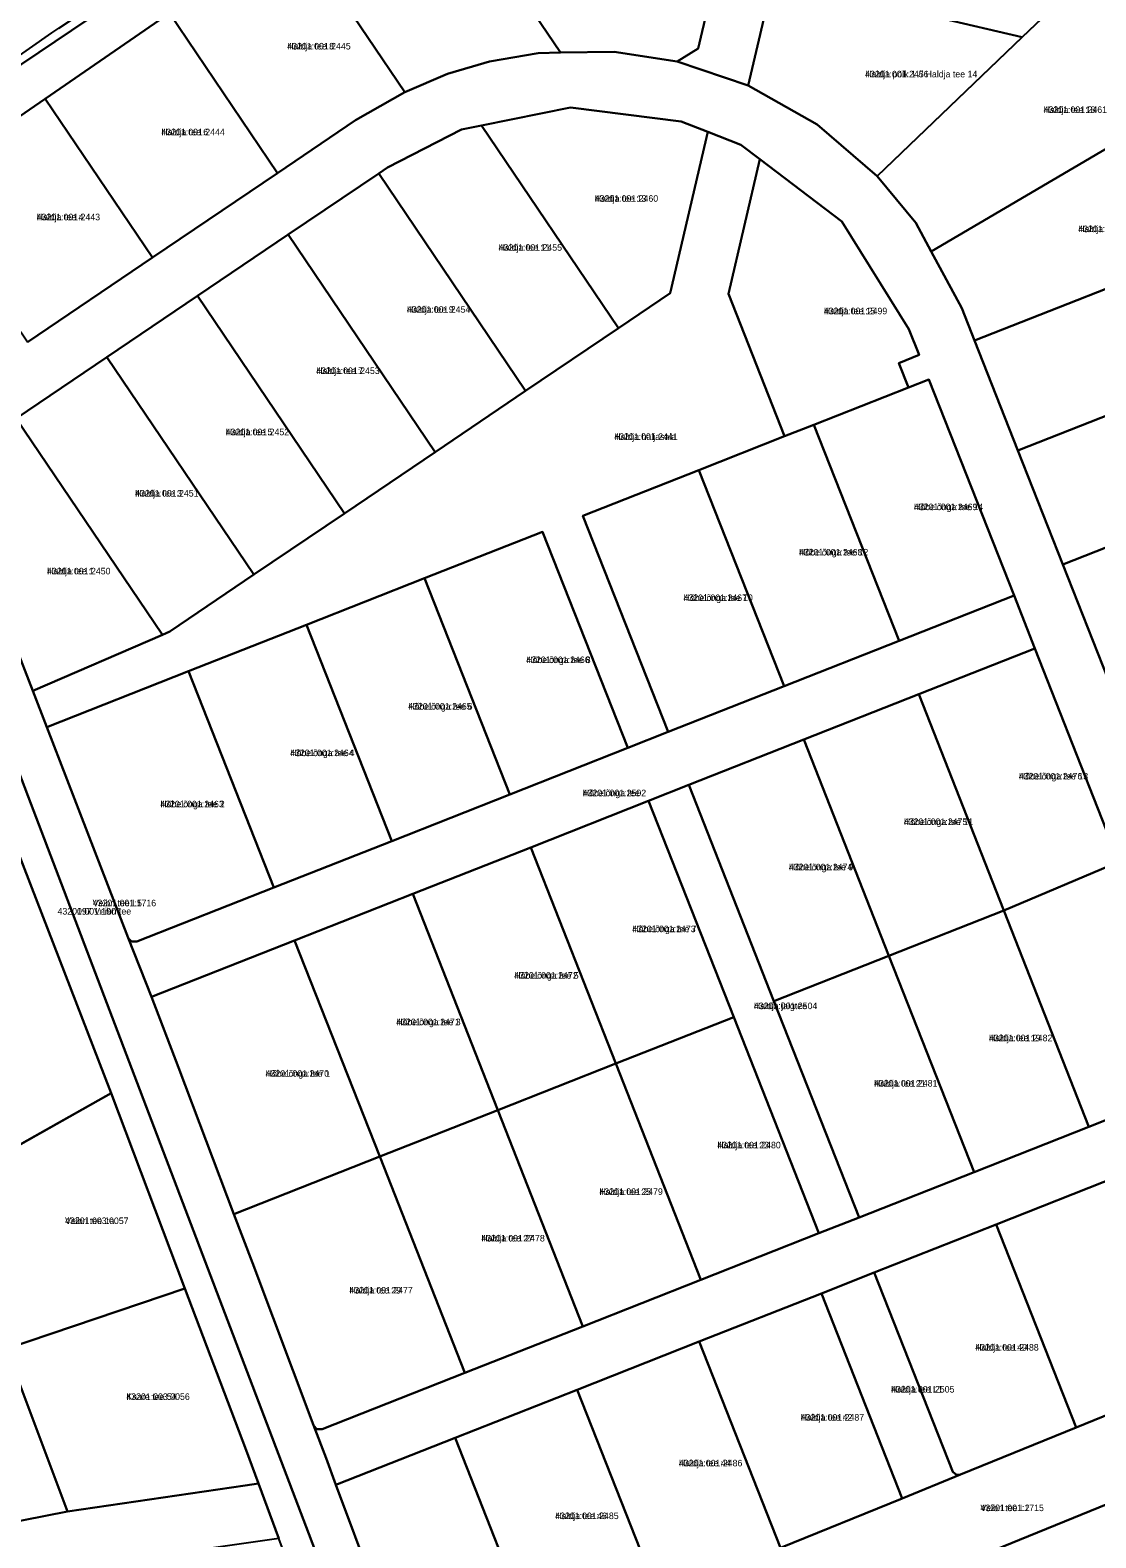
# Model space of a CAD drawing. Extents: x 661852 to 683758, y 6469495 to 6482657.
# Drawn here: x 663211.4 to 663455, y 6470005.7 to 6470350.3 of the extents above; entities that cross this region are included whole.
import ezdxf

# ---------------------------------------------------------------- set-up
doc = ezdxf.new("R2010")
doc.units = 0
for name, color, linetype in [('L_AADRESS', 7, 'Continuous'), ('PIIR', 7, 'Continuous'), ('TUNNUS', 7, 'Continuous')]:
    doc.layers.add(name, color=color, linetype=linetype)

msp = doc.modelspace()

# ---------------------------------------------------------------- linework, layer by layer
at = {"layer": 'PIIR'}
for points in [[(663386.73, 6470461.98), (663152.91, 6470304.5), (663149.63, 6470302.29), (663149.29, 6470302.91), (663152.5, 6470305.15), (663176.5, 6470321.88), (663197.37, 6470336.43), (663216.36, 6470349.67), (663217.96, 6470350.73), (663240.69, 6470365.84), (663264.21, 6470381.45), (663287.53, 6470396.88), (663309.62, 6470411.62), (663332.17, 6470426.61), (663387.19, 6470463.21), (663407.23, 6470476.53), (663407.44, 6470475.89), (663388.39, 6470463.06)], [(663384.15, 6470450.91), (663386.73, 6470461.98), (663388.39, 6470463.06), (663407.44, 6470475.89), (663408.76, 6470472.61), (663412.87, 6470462.32), (663404.89, 6470462.68), (663392.65, 6470410.54), (663386.56, 6470384.61), (663381.26, 6470362.01), (663375.54, 6470337.65), (663359.35, 6470343.1), (663364.16, 6470346.08), (663370.17, 6470371.68), (663376.34, 6470397.96), (663386.86, 6470442.78), (663382.48, 6470443.81)], [(663158.41, 6470295.77), (663152.91, 6470304.5), (663386.73, 6470461.98), (663384.15, 6470450.91), (663324.73, 6470410.08), (663300.15, 6470393.19), (663271.71, 6470373.65), (663243.28, 6470354.11), (663214.84, 6470334.57), (663186.41, 6470315.03)], [(663297.09, 6470336.11), (663271.71, 6470373.65), (663300.15, 6470393.19), (663304.22, 6470387.16), (663332.64, 6470345.13), (663327.57, 6470345.04), (663316.44, 6470343.1), (663306.8, 6470340.26)], [(663332.64, 6470345.13), (663304.22, 6470387.16), (663370.17, 6470371.68), (663364.16, 6470346.08), (663359.35, 6470343.1), (663344.92, 6470345.34)], [(663381.26, 6470362.01), (663386.56, 6470384.61), (663450.55, 6470369.61), (663453.21, 6470363), (663438.2, 6470348.65)], [(663267.97, 6470317.59), (663243.28, 6470354.11), (663271.71, 6470373.65), (663297.09, 6470336.11), (663285.82, 6470329.67)], [(663375.54, 6470337.65), (663381.26, 6470362.01), (663438.2, 6470348.65), (663405.06, 6470316.93), (663391.32, 6470328.73)], [(663413.86, 6470306.25), (663405.06, 6470316.93), (663438.2, 6470348.65), (663453.21, 6470363), (663455.55, 6470357.09), (663467.07, 6470328.89), (663417.42, 6470299.67)], [(663239.39, 6470298.27), (663214.84, 6470334.57), (663243.28, 6470354.11), (663267.97, 6470317.59)], [(663210.81, 6470278.94), (663186.41, 6470315.03), (663214.84, 6470334.57), (663239.39, 6470298.27)], [(663345.91, 6470282.17), (663314.59, 6470328.5), (663334.97, 6470332.56), (663360.25, 6470329.42), (663366.37, 6470327.01), (663357.72, 6470290.16)], [(663424.41, 6470286.73), (663417.42, 6470299.67), (663467.07, 6470328.89), (663468.95, 6470324.34), (663478.9, 6470299.63), (663427.33, 6470279.31)], [(663215.25, 6470190.94), (663212.02, 6470199.23), (663241.66, 6470212.1), (663243.38, 6470212.85), (663262.56, 6470225.82), (663283.27, 6470239.82), (663303.98, 6470253.83), (663324.69, 6470267.83), (663345.91, 6470282.17), (663357.72, 6470290.16), (663366.37, 6470327.01), (663373.89, 6470324.05), (663378.25, 6470320.75), (663371.03, 6470290.01), (663383.88, 6470257.44), (663364.29, 6470249.72), (663337.78, 6470239.26), (663357.24, 6470189.86), (663348.03, 6470186.23), (663328.57, 6470235.63), (663301.59, 6470224.99), (663274.61, 6470214.37), (663247.63, 6470203.74)], [(663324.69, 6470267.83), (663291.09, 6470317.53), (663293.08, 6470318.88), (663309.99, 6470327.59), (663314.59, 6470328.5), (663345.91, 6470282.17)], [(663371.03, 6470290.01), (663378.25, 6470320.75), (663396.98, 6470306.54), (663412.31, 6470281.96), (663414.65, 6470276.03), (663410, 6470274.19), (663412.2, 6470268.61), (663390.57, 6470260.08), (663383.88, 6470257.44)], [(663303.98, 6470253.83), (663270.38, 6470303.53), (663291.09, 6470317.53), (663324.69, 6470267.83)], [(663141.14, 6470297.18), (663149.29, 6470302.91), (663149.63, 6470302.29), (663172.11, 6470259.03), (663199.81, 6470204.15), (663290.64, 6469965.78), (663294.2, 6469956.47), (663287.39, 6469954.31), (663283.33, 6469965.26), (663268.3, 6470005.53), (663263.62, 6470018.08), (663260.78, 6470025.7), (663246.79, 6470062.71), (663229.93, 6470107.3), (663192.84, 6470203.14), (663189.45, 6470209.31), (663163, 6470257.41), (663157.47, 6470267.48)], [(663257.98, 6470079.68), (663262.23, 6470068.54), (663276.21, 6470031.4), (663279.07, 6470023.87), (663281.32, 6470017.82), (663298.51, 6469971.76), (663301.8, 6469970.32), (663290.64, 6469965.78), (663199.81, 6470204.15), (663172.11, 6470259.03), (663149.63, 6470302.29), (663152.91, 6470304.5), (663158.41, 6470295.77), (663177.46, 6470265.36), (663207.83, 6470210.12), (663212.02, 6470199.23), (663215.25, 6470190.94), (663233.85, 6470142.82), (663239.14, 6470129.31), (663245.34, 6470113.2)], [(663283.27, 6470239.82), (663249.67, 6470289.53), (663270.38, 6470303.53), (663303.98, 6470253.83)], [(663437.22, 6470254.19), (663427.33, 6470279.31), (663478.9, 6470299.63), (663481.61, 6470292.92), (663489.08, 6470274.65)], [(663262.56, 6470225.82), (663228.96, 6470275.52), (663249.67, 6470289.53), (663283.27, 6470239.82)], [(663241.66, 6470212.1), (663208.25, 6470261.52), (663228.96, 6470275.52), (663262.56, 6470225.82), (663243.38, 6470212.85)], [(663447.51, 6470228.15), (663437.22, 6470254.19), (663489.08, 6470274.65), (663490.85, 6470270.27), (663494.85, 6470259.49), (663498.91, 6470248.41)], [(663410.05, 6470210.68), (663390.57, 6470260.08), (663412.2, 6470268.61), (663416.85, 6470270.44), (663436.33, 6470221.05)], [(663192.07, 6470242.07), (663189.07, 6470246.85), (663188.9, 6470247.94), (663189.52, 6470248.86), (663208.25, 6470261.52), (663241.66, 6470212.1), (663212.02, 6470199.23), (663207.83, 6470210.12)], [(663383.77, 6470200.32), (663364.29, 6470249.72), (663383.88, 6470257.44), (663390.57, 6470260.08), (663410.05, 6470210.68)], [(663357.24, 6470189.86), (663337.78, 6470239.26), (663364.29, 6470249.72), (663383.77, 6470200.32)], [(663457.77, 6470202.1), (663447.51, 6470228.15), (663498.91, 6470248.41), (663506.83, 6470226.65), (663508.52, 6470222.1)], [(663321.05, 6470175.59), (663301.59, 6470224.99), (663328.57, 6470235.63), (663348.03, 6470186.23)], [(663294.07, 6470164.94), (663274.61, 6470214.37), (663301.59, 6470224.99), (663321.05, 6470175.59)], [(663239.14, 6470129.31), (663233.85, 6470142.82), (663234.67, 6470142), (663235.82, 6470141.98), (663267.09, 6470154.31), (663294.07, 6470164.94), (663321.05, 6470175.59), (663348.03, 6470186.23), (663357.24, 6470189.86), (663383.77, 6470200.32), (663410.05, 6470210.68), (663436.33, 6470221.05), (663441.1, 6470208.95), (663414.54, 6470198.48), (663388.27, 6470188.12), (663362, 6470177.76), (663352.79, 6470174.13), (663325.84, 6470163.5), (663298.86, 6470152.87), (663271.88, 6470142.23)], [(663267.09, 6470154.31), (663247.63, 6470203.74), (663274.61, 6470214.37), (663294.07, 6470164.94)], [(663434, 6470149.07), (663414.54, 6470198.48), (663441.1, 6470208.95), (663460.32, 6470160.22)], [(663192.84, 6470203.14), (663229.93, 6470107.3), (663166.15, 6470071.45), (663135.61, 6470146.35)], [(663233.85, 6470142.82), (663215.25, 6470190.94), (663247.63, 6470203.74), (663267.09, 6470154.31), (663235.82, 6470141.98), (663234.67, 6470142)], [(663407.72, 6470138.71), (663388.27, 6470188.12), (663414.54, 6470198.48), (663434, 6470149.07)], [(663381.45, 6470128.35), (663362, 6470177.76), (663388.27, 6470188.12), (663407.72, 6470138.71)], [(663372.24, 6470124.72), (663352.79, 6470174.13), (663362, 6470177.76), (663381.45, 6470128.35), (663400.91, 6470078.93), (663391.7, 6470075.3)], [(663345.3, 6470114.1), (663325.84, 6470163.5), (663352.79, 6470174.13), (663372.24, 6470124.72)], [(663318.32, 6470103.45), (663298.86, 6470152.87), (663325.84, 6470163.5), (663345.3, 6470114.1)], [(663453.46, 6470099.65), (663434, 6470149.07), (663460.32, 6470160.22), (663476.4, 6470119.44), (663476.27, 6470111.79), (663470.76, 6470106.47)], [(663291.34, 6470092.82), (663271.88, 6470142.23), (663298.86, 6470152.87), (663318.32, 6470103.45)], [(663427.19, 6470089.29), (663407.72, 6470138.71), (663434, 6470149.07), (663453.46, 6470099.65)], [(663245.34, 6470113.2), (663239.14, 6470129.31), (663271.88, 6470142.23), (663291.34, 6470092.82), (663257.98, 6470079.68)], [(663400.91, 6470078.93), (663381.45, 6470128.35), (663407.72, 6470138.71), (663427.19, 6470089.29)], [(663364.76, 6470064.67), (663345.3, 6470114.1), (663372.24, 6470124.72), (663391.7, 6470075.3)], [(663337.78, 6470054.02), (663318.32, 6470103.45), (663345.3, 6470114.1), (663364.76, 6470064.67)], [(663229.93, 6470107.3), (663246.79, 6470062.71), (663206, 6470048.85), (663192.04, 6470086)], [(663310.8, 6470043.39), (663291.34, 6470092.82), (663318.32, 6470103.45), (663337.78, 6470054.02)], [(663262.23, 6470068.54), (663257.98, 6470079.68), (663291.34, 6470092.82), (663310.8, 6470043.39), (663278.19, 6470030.53), (663277.03, 6470030.56), (663276.21, 6470031.4)], [(663450.57, 6470030.92), (663432.28, 6470077.32), (663460.38, 6470088.4), (663478.56, 6470042.34)], [(663192.04, 6470086), (663206, 6470048.85), (663219.96, 6470011.7), (663190.11, 6470005.84), (663165.58, 6470071.13), (663166.15, 6470071.45)], [(663422.34, 6470020.76), (663404.37, 6470066.32), (663432.28, 6470077.32), (663450.57, 6470030.92), (663424.13, 6470020.15), (663423.15, 6470020.12)], [(663410.76, 6470014.71), (663392.28, 6470061.55), (663404.37, 6470066.32), (663422.34, 6470020.76), (663423.15, 6470020.12), (663424.13, 6470020.15)], [(663246.79, 6470062.71), (663260.78, 6470025.7), (663263.62, 6470018.08), (663260.55, 6470017.63), (663219.96, 6470011.7), (663206, 6470048.85)], [(663382.98, 6470003.39), (663364.37, 6470050.54), (663392.28, 6470061.55), (663410.76, 6470014.71)], [(663354.31, 6469994.3), (663336.46, 6470039.54), (663364.37, 6470050.54), (663382.98, 6470003.39), (663364.1, 6469995.69), (663356.08, 6469995.02)], [(663327.39, 6469980.73), (663308.56, 6470028.53), (663336.46, 6470039.54), (663354.31, 6469994.3), (663352.17, 6469993.43), (663345.96, 6469988.31)], [(663298.51, 6469971.76), (663281.32, 6470017.82), (663308.56, 6470028.53), (663327.39, 6469980.73), (663301.8, 6469970.32)], [(663442.36, 6469969.84), (663429.7, 6470002), (663457.78, 6470013.44), (663469.01, 6470019.52), (663482.37, 6469985.59)]]:
    msp.add_lwpolyline(points, close=True, dxfattribs=at)
for points in [[(663210.81, 6470278.94), (663239.39, 6470298.27), (663267.97, 6470317.59), (663285.82, 6470329.67), (663297.09, 6470336.11), (663306.8, 6470340.26), (663316.44, 6470343.1), (663327.57, 6470345.04), (663332.64, 6470345.13), (663344.92, 6470345.34), (663359.35, 6470343.1), (663375.54, 6470337.65), (663391.32, 6470328.73), (663405.06, 6470316.93), (663413.86, 6470306.25), (663417.42, 6470299.67), (663424.41, 6470286.73), (663427.33, 6470279.31), (663437.22, 6470254.19), (663447.51, 6470228.15), (663457.77, 6470202.1)], [(663460.32, 6470160.22), (663441.1, 6470208.95), (663436.33, 6470221.05), (663416.85, 6470270.44), (663412.2, 6470268.61), (663410, 6470274.19), (663414.65, 6470276.03), (663412.31, 6470281.96), (663396.98, 6470306.54), (663378.25, 6470320.75), (663373.89, 6470324.05), (663366.37, 6470327.01), (663360.25, 6470329.42), (663334.97, 6470332.56), (663314.59, 6470328.5), (663309.99, 6470327.59), (663293.08, 6470318.88), (663291.09, 6470317.53), (663270.38, 6470303.53), (663249.67, 6470289.53), (663228.96, 6470275.52), (663208.25, 6470261.52)], [(663460.38, 6470088.4), (663432.28, 6470077.32), (663404.37, 6470066.32), (663392.28, 6470061.55), (663364.37, 6470050.54), (663336.46, 6470039.54), (663308.56, 6470028.53), (663281.32, 6470017.82), (663279.07, 6470023.87), (663276.21, 6470031.4), (663277.03, 6470030.56), (663278.19, 6470030.53), (663310.8, 6470043.39), (663337.78, 6470054.02), (663364.76, 6470064.67), (663391.7, 6470075.3), (663400.91, 6470078.93), (663427.19, 6470089.29), (663453.46, 6470099.65), (663470.76, 6470106.47)], [(663382.98, 6470003.39), (663410.76, 6470014.71), (663424.13, 6470020.15), (663450.57, 6470030.92), (663478.56, 6470042.34), (663506.34, 6470053.64), (663556.66, 6470074.15), (663558.1, 6470069.62), (663561.41, 6470059.24), (663562.22, 6470057.44), (663518.75, 6470039.77), (663472.72, 6470021.03), (663469.01, 6470019.52), (663457.78, 6470013.44), (663429.7, 6470002)], [(663190.11, 6470005.84), (663219.96, 6470011.7), (663260.55, 6470017.63), (663263.62, 6470018.08), (663268.3, 6470005.53), (663224.61, 6469999.31), (663194.73, 6469993.53)]]:
    msp.add_lwpolyline(points, dxfattribs=at)

# ---------------------------------------------------------------- texts
at = {"layer": 'L_AADRESS'}
for s, p in [('Haldja tee 8', (663270.19, 6470345.85)), ('Haldja põik 1 // Haldja tee 14', (663402.29, 6470339.47)), ('Haldja tee 16', (663443.09, 6470331.34)), ('Haldja tee 6', (663241.41, 6470326.23)), ('Haldja tee 13', (663340.48, 6470311.04)), ('Haldja tee 4', (663212.9, 6470306.8)), ('Haldja tee 18', (663451.02, 6470304.1)), ('Haldja tee 11', (663318.5, 6470299.85)), ('Haldja tee 9', (663297.54, 6470285.68)), ('Haldja tee 15', (663392.84, 6470285.33)), ('Haldja tee 7', (663276.82, 6470271.68)), ('Haldja tee 5', (663256.12, 6470257.67)), ('Haldja haljasala', (663344.95, 6470256.62)), ('Haldja tee 3', (663235.41, 6470243.67)), ('Hõbelõnga tee 14', (663413.45, 6470240.56)), ('Hõbelõnga tee 12', (663387.17, 6470230.2)), ('Haldja tee 1', (663215.28, 6470225.88)), ('Hõbelõnga tee 10', (663360.78, 6470219.79)), ('Hõbelõnga tee 8', (663324.81, 6470205.61)), ('Hõbelõnga tee 6', (663297.83, 6470194.97)), ('Hõbelõnga tee 4', (663270.85, 6470184.34)), ('Hõbelõnga tee 13', (663437.43, 6470179.01)), ('Hõbelõnga tee 2', (663241.17, 6470172.64)), ('Hõbelõnga tee', (663337.73, 6470175.18)), ('Hõbelõnga tee 11', (663411.14, 6470168.6)), ('Hõbelõnga tee 9', (663384.86, 6470158.24)), ('4320097 Veibri tee', (663217.67, 6470148.13)), ('Veibri tee L5', (663225.71, 6470150.02)), ('Hõbelõnga tee 7', (663349.04, 6470144.11)), ('Hõbelõnga tee 5', (663322.08, 6470133.48)), ('Haldja jalgtee', (663376.85, 6470126.52)), ('Hõbelõnga tee 3', (663295.1, 6470122.84)), ('Haldja tee 19', (663430.59, 6470119.18)), ('Hõbelõnga tee 1', (663265.24, 6470111.07)), ('Haldja tee 21', (663404.32, 6470108.82)), ('Haldja tee 23', (663368.5, 6470094.7)), ('Haldja tee 25', (663341.54, 6470084.06)), ('Veibri tee 1a', (663219.41, 6470077.4)), ('Haldja tee 27', (663314.56, 6470073.42)), ('Haldja tee 29', (663284.39, 6470061.53)), ('Haldja tee 40', (663427.47, 6470048.47)), ('Haldja tee L1', (663408.21, 6470038.89)), ('Kaare tee 54', (663233.4, 6470037.21)), ('Haldja tee 42', (663387.56, 6470032.47)), ('Haldja tee 44', (663359.72, 6470022.02)), ('Veibri tee L2', (663428.65, 6470011.79)), ('Haldja tee 46', (663331.44, 6470009.97))]:
    msp.add_text(s, height=1.5, dxfattribs=at).set_placement(p)
at = {"layer": 'TUNNUS'}
for s, p in [('43201:001:2445', (663270.19, 6470345.85)), ('43201:001:2456', (663402.29, 6470339.47)), ('43201:001:2461', (663443.09, 6470331.34)), ('43201:001:2444', (663241.41, 6470326.23)), ('43201:001:2460', (663340.48, 6470311.04)), ('43201:001:2443', (663212.9, 6470306.8)), ('43201:001:2462', (663451.02, 6470304.1)), ('43201:001:2455', (663318.5, 6470299.85)), ('43201:001:2454', (663297.54, 6470285.68)), ('43201:001:2499', (663392.84, 6470285.33)), ('43201:001:2453', (663276.82, 6470271.68)), ('43201:001:2452', (663256.12, 6470257.67)), ('43201:001:2441', (663344.95, 6470256.62)), ('43201:001:2451', (663235.41, 6470243.67)), ('43201:001:2469', (663413.45, 6470240.56)), ('43201:001:2468', (663387.17, 6470230.2)), ('43201:001:2450', (663215.28, 6470225.88)), ('43201:001:2467', (663360.78, 6470219.79)), ('43201:001:2466', (663324.81, 6470205.61)), ('43201:001:2465', (663297.83, 6470194.97)), ('43201:001:2464', (663270.85, 6470184.34)), ('43201:001:2476', (663437.43, 6470179.01)), ('43201:001:2463', (663241.17, 6470172.64)), ('43201:001:2502', (663337.73, 6470175.18)), ('43201:001:2475', (663411.14, 6470168.6)), ('43201:001:2474', (663384.86, 6470158.24)), ('43201:001:1907', (663217.67, 6470148.13)), ('43201:001:1716', (663225.71, 6470150.02)), ('43201:001:2473', (663349.04, 6470144.11)), ('43201:001:2472', (663322.08, 6470133.48)), ('43201:001:2504', (663376.85, 6470126.52)), ('43201:001:2471', (663295.1, 6470122.84)), ('43201:001:2482', (663430.59, 6470119.18)), ('43201:001:2470', (663265.24, 6470111.07)), ('43201:001:2481', (663404.32, 6470108.82)), ('43201:001:2480', (663368.5, 6470094.7)), ('43201:001:2479', (663341.54, 6470084.06)), ('43201:003:0057', (663219.41, 6470077.4)), ('43201:001:2478', (663314.56, 6470073.42)), ('43201:001:2477', (663284.39, 6470061.53)), ('43201:001:2488', (663427.47, 6470048.47)), ('43201:001:2505', (663408.21, 6470038.89)), ('43201:003:0056', (663233.4, 6470037.21)), ('43201:001:2487', (663387.56, 6470032.47)), ('43201:001:2486', (663359.72, 6470022.02)), ('43201:001:1715', (663428.65, 6470011.79)), ('43201:001:2485', (663331.44, 6470009.97))]:
    msp.add_text(s, height=1.5, dxfattribs=at).set_placement(p)

doc.saveas('drawing.dxf')
